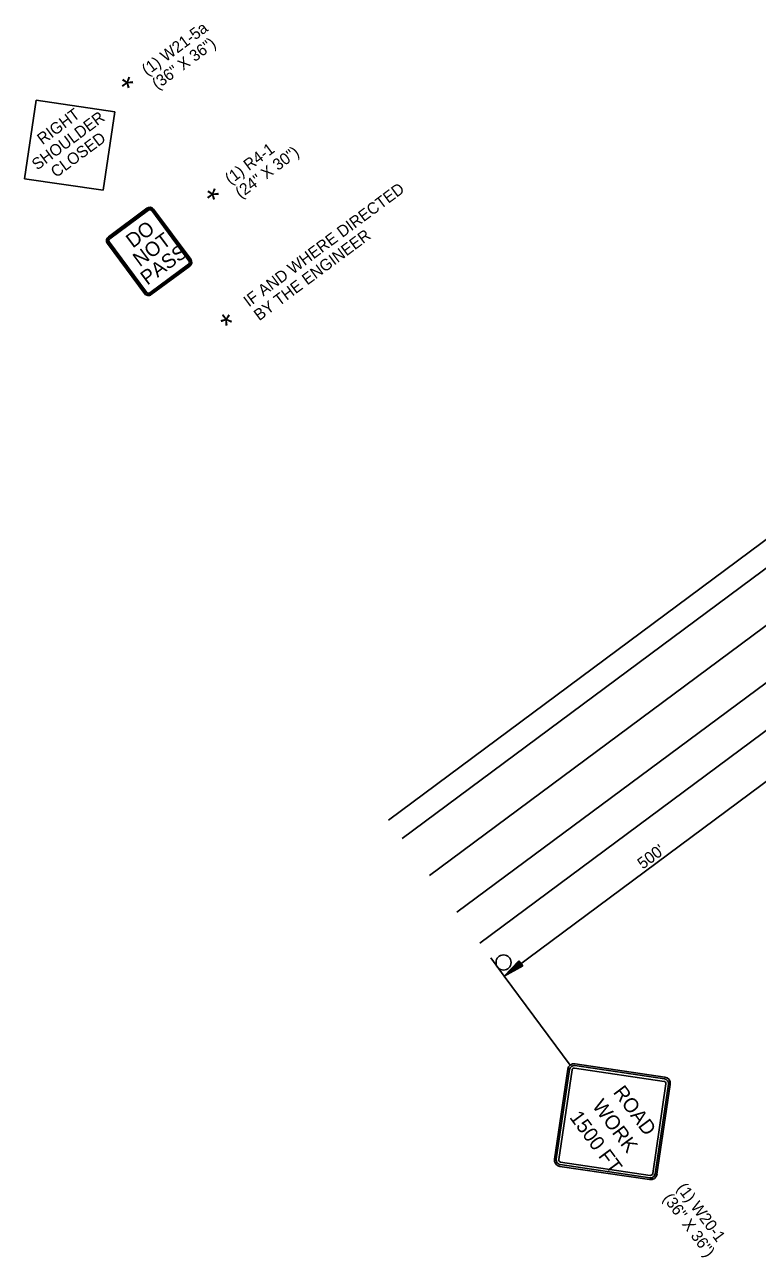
# Model space of a CAD drawing. Extents: x 998982 to 1000626, y 1875366 to 1876934.
# Drawn here: x 998982 to 999363, y 1875366 to 1876008 of the extents above; entities that cross this region are included whole.
import ezdxf

# ---------------------------------------------------------------- set-up
doc = ezdxf.new("R2010")
doc.units = 0
for name, color, linetype in [('P_TC_Signs_Permanent', 7, 'Continuous'), ('P_TC_Signs_Temporary', 7, 'Continuous'), ('R_Border Prem', 7, 'Continuous'), ('R_Draft', 7, 'Continuous'), ('STAMP', 7, 'Continuous')]:
    doc.layers.add(name, color=color, linetype=linetype)

msp = doc.modelspace()

# ---------------------------------------------------------------- linework, layer by layer
at = {"layer": 'P_TC_Signs_Permanent'}
for p, q in [((999045.36, 1875912.28), (999025.29, 1875897.37)), ((999045.66, 1875911.88), (999025.59, 1875896.97)), ((999046.11, 1875911.27), (999026.04, 1875896.37)), ((999067.23, 1875884.92), (999047.86, 1875911.01)), ((999067.83, 1875885.37), (999048.46, 1875911.46)), ((999068.23, 1875885.67), (999048.86, 1875911.76)), ((999024.77, 1875893.88), (999044.15, 1875867.78)), ((999025.17, 1875894.17), (999044.55, 1875868.08)), ((999025.78, 1875894.62), (999045.15, 1875868.53)), ((999046.9, 1875868.27), (999066.97, 1875883.17)), ((999047.35, 1875867.67), (999067.42, 1875882.57)), ((999047.65, 1875867.27), (999067.72, 1875882.17))]:
    msp.add_line(p, q, dxfattribs=at)
for centre, radius, start, end in [((999046.85, 1875910.27), 2.5, 36.59533, 126.59533), ((999046.85, 1875910.27), 2, 36.59533, 126.59533), ((999046.85, 1875910.27), 1.25, 36.59533, 126.59533), ((999026.78, 1875895.37), 2.5, 126.59533, 216.59533), ((999026.78, 1875895.37), 2, 126.59533, 216.59533), ((999026.78, 1875895.37), 1.25, 126.59533, 216.59533), ((999066.23, 1875884.18), 1.25, 306.59533, 36.59533), ((999066.23, 1875884.18), 2, 306.59533, 36.59533), ((999066.23, 1875884.18), 2.5, 306.59533, 36.59533), ((999046.16, 1875869.27), 2.5, 216.59533, 306.59533), ((999046.16, 1875869.27), 2, 216.59533, 306.59533), ((999046.16, 1875869.27), 1.25, 216.59533, 306.59533)]:
    msp.add_arc(centre, radius, start, end, dxfattribs=at)
at = {"layer": 'P_TC_Signs_Temporary'}
for p, q in [((999268.32, 1875465.63), (999315.06, 1875458.73)), ((999268.46, 1875466.56), (999315.2, 1875459.66)), ((999257.72, 1875416.97), (999264.63, 1875463.72)), ((999258.65, 1875416.84), (999265.55, 1875463.58)), ((999259.94, 1875416.65), (999266.85, 1875463.39)), ((999268.13, 1875464.34), (999314.87, 1875457.43)), ((999315.82, 1875456.15), (999308.91, 1875409.41)), ((999317.12, 1875455.96), (999310.21, 1875409.22)), ((999318.05, 1875455.82), (999311.14, 1875409.08)), ((999307.31, 1875406.24), (999260.56, 1875413.14)), ((999307.44, 1875407.16), (999260.7, 1875414.07)), ((999307.64, 1875408.46), (999260.89, 1875415.37))]:
    msp.add_line(p, q, dxfattribs=at)
for centre, radius, start, end in [((999267.96, 1875463.22), 3.38, 81.59533, 171.59533), ((999267.96, 1875463.22), 2.44, 81.59533, 171.59533), ((999267.96, 1875463.22), 1.12, 81.59533, 171.59533), ((999314.71, 1875456.32), 2.44, 351.59533, 81.59533), ((999314.71, 1875456.32), 3.38, 351.59533, 81.59533), ((999314.71, 1875456.32), 1.13, 351.59533, 81.59533), ((999261.06, 1875416.48), 3.38, 171.59533, 261.59533), ((999261.06, 1875416.48), 2.44, 171.59533, 261.59533), ((999261.06, 1875416.48), 1.13, 171.59533, 261.59533), ((999307.8, 1875409.57), 3.38, 261.59533, 351.59533), ((999307.8, 1875409.57), 2.44, 261.59533, 351.59533), ((999307.8, 1875409.57), 1.12, 261.59533, 351.59533)]:
    msp.add_arc(centre, radius, start, end, dxfattribs=at)
at = {"layer": 'R_Border Prem'}
for p, q in [((998987.69, 1875968.55), (998981.64, 1875927.64)), ((999028.6, 1875962.5), (998987.69, 1875968.55)), ((999028.6, 1875962.5), (999022.54, 1875921.61)), ((999022.54, 1875921.61), (998981.64, 1875927.64))]:
    msp.add_line(p, q, dxfattribs=at)
at = {"layer": 'R_Draft'}
for p, q in [((999192.61, 1875564.71), (999743.69, 1875973.9)), ((999171.2, 1875593.53), (999643.2, 1875944.01)), ((999178.34, 1875583.93), (999650.33, 1875934.4)), ((999206.88, 1875545.49), (999678.87, 1875895.96)), ((999218.77, 1875529.47), (999690.77, 1875879.94)), ((999392.1, 1875631.53), (999231.53, 1875512.3)), ((999239.16, 1875520.22), (999231.53, 1875512.3)), ((999241.15, 1875517.63), (999231.53, 1875512.3)), ((999239.33, 1875520), (999232.97, 1875513.41)), ((999240.98, 1875517.84), (999232.97, 1875513.41)), ((999239.5, 1875519.78), (999234.45, 1875514.54)), ((999240.81, 1875518.06), (999234.45, 1875514.54)), ((999239.66, 1875519.56), (999235.89, 1875515.65)), ((999240.65, 1875518.28), (999235.89, 1875515.65)), ((999239.83, 1875519.35), (999237.35, 1875516.77)), ((999240.48, 1875518.5), (999237.35, 1875516.77)), ((999240, 1875519.13), (999238.79, 1875517.88)), ((999240.31, 1875518.72), (999238.79, 1875517.88)), ((999241.15, 1875517.63), (999239.16, 1875520.22)), ((999231.53, 1875512.3), (999265.95, 1875465.93))]:
    msp.add_line(p, q, dxfattribs=at)
at = {"layer": 'STAMP'}
msp.add_line((999231.53, 1875512.3), (999224.53, 1875521.74), dxfattribs=at)
msp.add_circle((999231.17, 1875519.35), 3.92, dxfattribs=at)

# ---------------------------------------------------------------- texts
at = {"layer": 'P_TC_Signs_Permanent'}
for s, rotation, p in [('DO', 36.59533, (999037.98, 1875891.23)), ('NOT', 36.55497, (999041.61, 1875881.47)), ('PASS', 36.59533, (999045.53, 1875871.92))]:
    msp.add_text(s, height=7.5, rotation=rotation, dxfattribs=at).set_placement(p)
at = {"layer": 'P_TC_Signs_Temporary'}
for s, p in [(' ROAD ', (999286.32, 1875453.95)), ('WORK', (999277.08, 1875444.56)), ('1500 FT', (999265.25, 1875438.64))]:
    msp.add_text(s, height=7.5, rotation=306.59533, dxfattribs=at).set_placement(p)
at = {"layer": 'R_Border Prem'}
for s, height, rotation, p in [('(1) W21-5a', 6, 36.59533, (999045.44, 1875981.06)), ('(36" X 36")', 6, 36.59533, (999050.8, 1875973.84)), ('*', 12, 126.59533, (999044, 1875980.47)), ('SHOULDER', 6, 36.59577, (998988.19, 1875931.83)), ('RIGHT ', 6, 36.59577, (998990.95, 1875945.08)), ('CLOSED', 6, 36.59577, (998998.04, 1875927.93)), ('(1) R4-1', 6, 36.59533, (999088.82, 1875924.37)), ('(24" X 30")', 6, 36.59533, (999094.18, 1875917.15)), ('*', 12, 126.59533, (999088.5, 1875922.32)), ('IF AND WHERE DIRECTED ', 6, 36.59533, (999098.51, 1875860.57)), ('BY THE ENGINEER', 6, 36.59533, (999103.87, 1875853.35)), ('*', 12, 36.59533, (999089.4, 1875845.33)), ("500'", 6, 36.59533, (999303.72, 1875567.68)), ('(1) W20-1', 6, 306.59533, (999321.18, 1875401.78)), ('(36" X 36")', 6, 306.59533, (999313.95, 1875396.41))]:
    msp.add_text(s, height=height, rotation=rotation, dxfattribs=at).set_placement(p)

doc.saveas('drawing.dxf')
